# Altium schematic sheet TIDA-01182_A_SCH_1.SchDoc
size 431 x 279 mm; Date: Not shown in title block; ApprovedBy: Not shown in title block; CheckedBy: Not shown in title block; Author: Not shown in title block; CompanyName: Not shown in title block; DrawnBy: Gordon Varney; Engineer: Not shown in title block; Organization: Not shown in title block; Address1: Not shown in title block; Address2: Not shown in title block; Address3: Not shown in title block; Address4: Not shown in title block; DocumentNumber: 1; Revision: Use project parameter SCH_Rev; SheetNumber: 2; SheetTotal: 4; PageSetup: Record=PageOptions¦CenterHorizontal=True¦CenterVertical=True¦PrintScale=0.70¦XCorrection=1.00¦YCorrection=1.00¦PrintKind=0¦BorderSize=5000000¦LeftOffset=0¦BottomOffset=0¦Orientation=2¦PaperLength=1000¦PaperWidth=1000¦Scale=100¦PaperSource=15¦PrintQuality=1200¦MediaType=1¦DitherType=10¦PrintScaleMode=1¦PaperKind=Letter¦PaperIndex=1
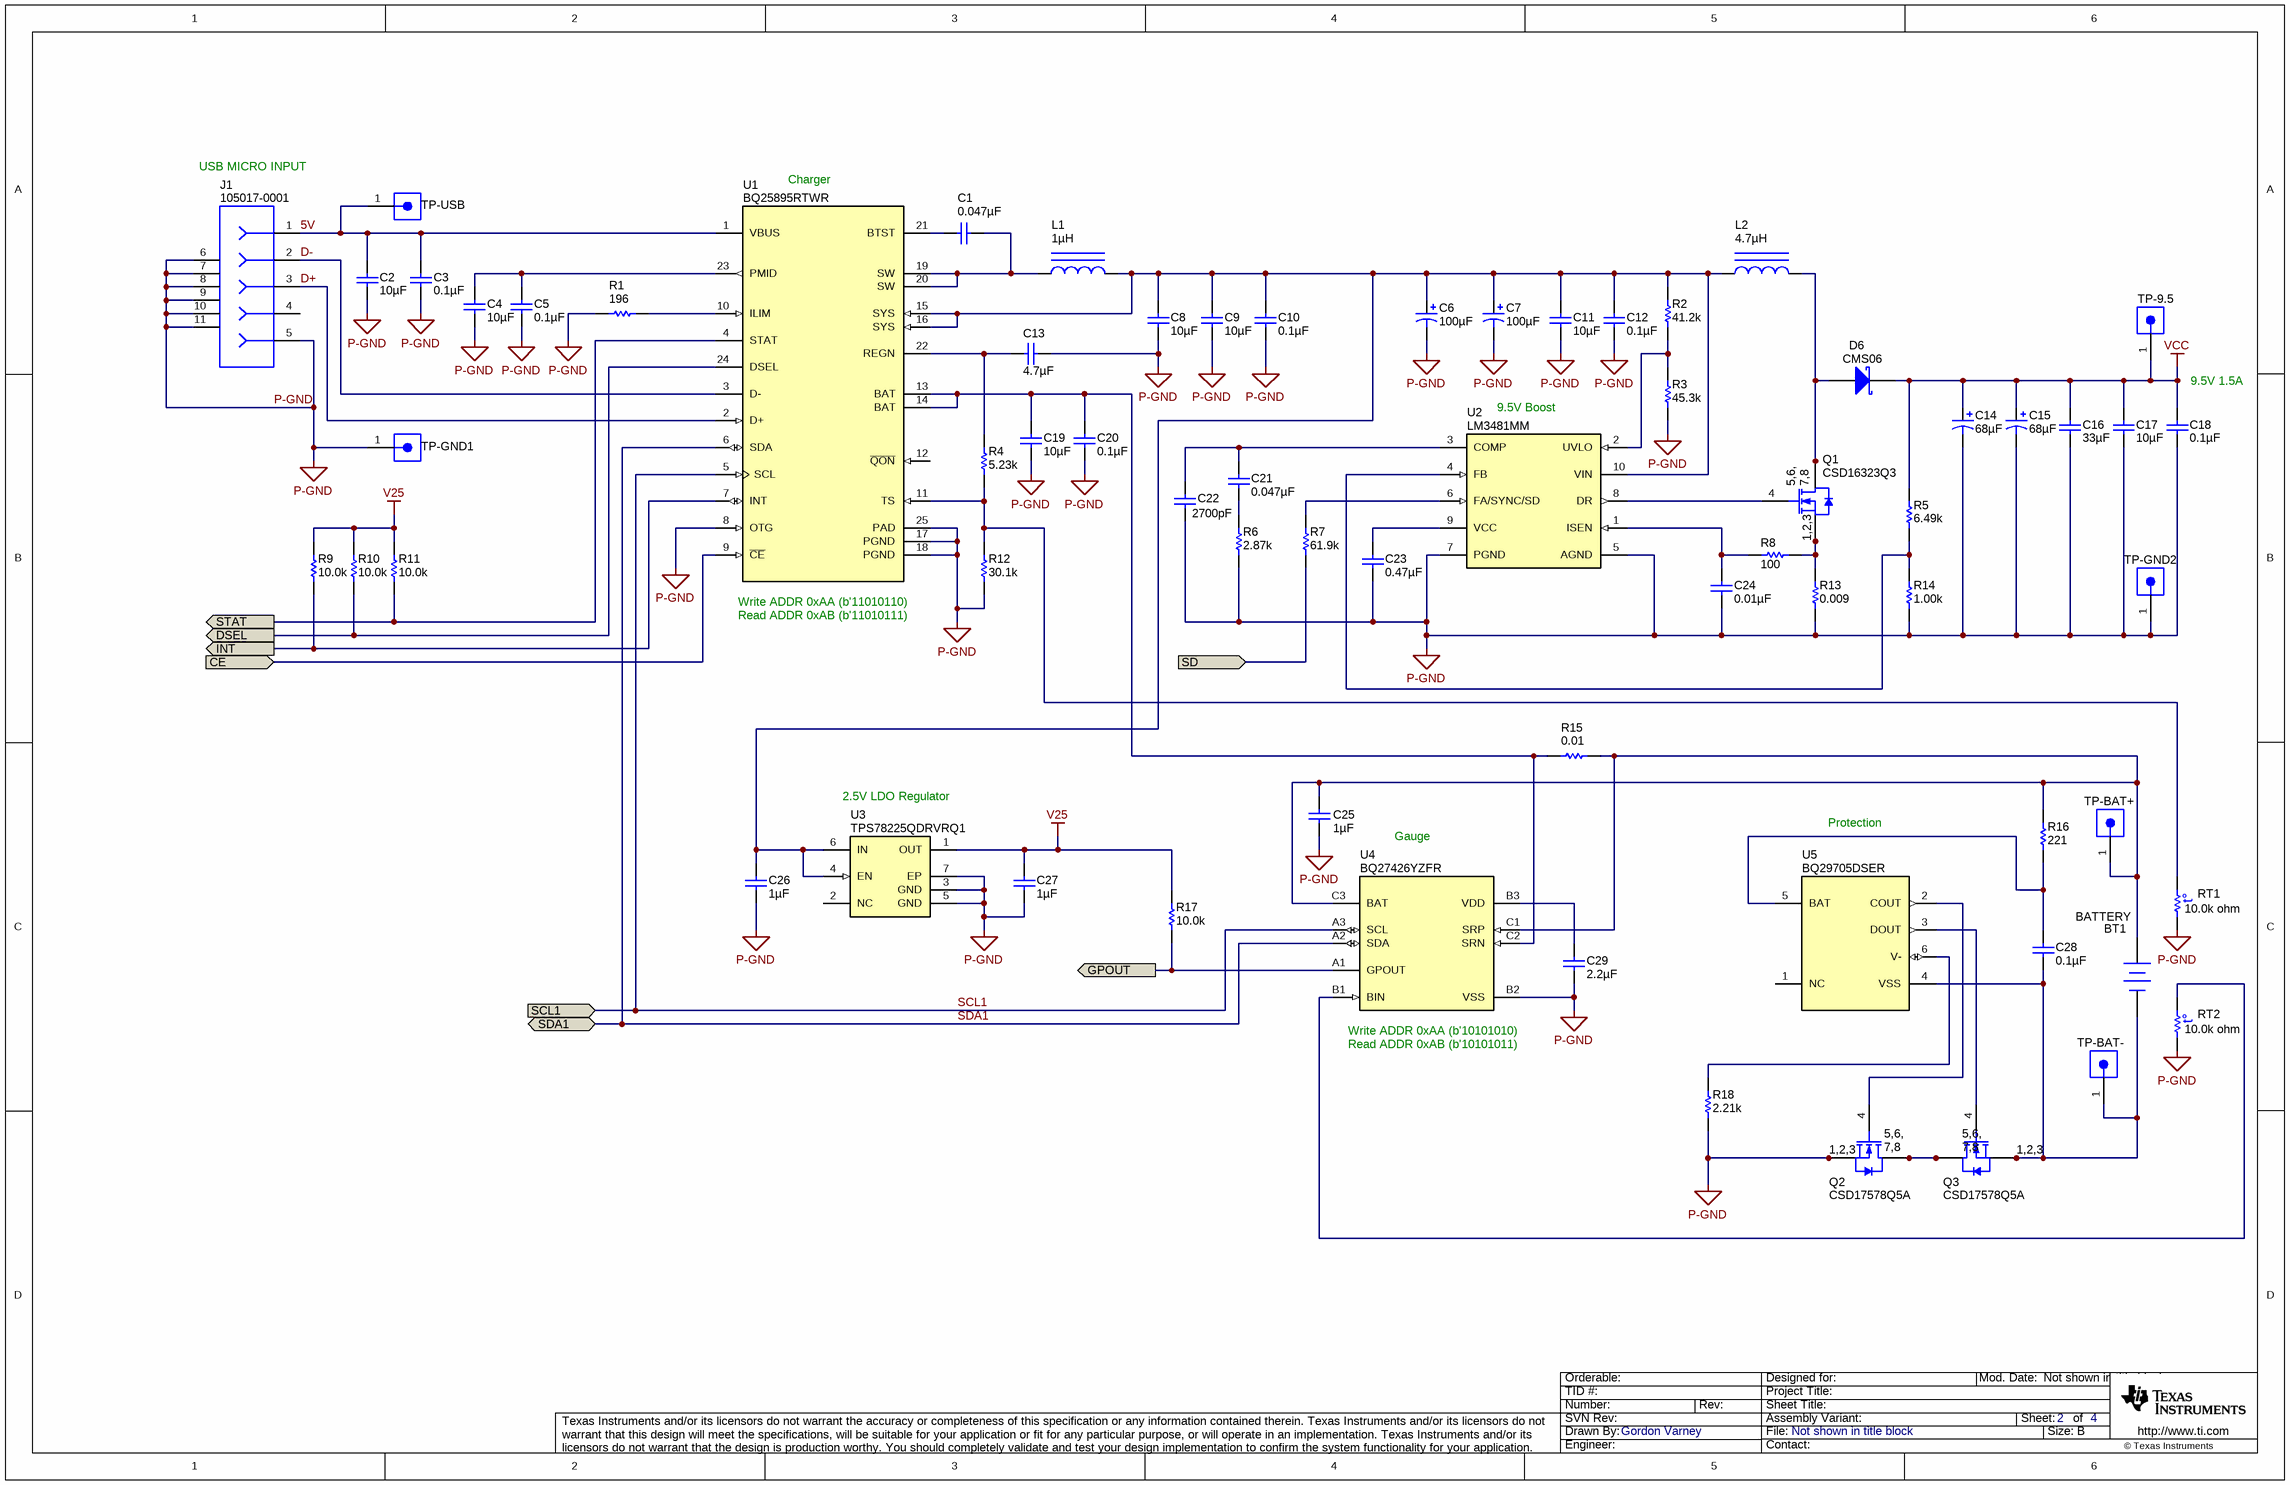
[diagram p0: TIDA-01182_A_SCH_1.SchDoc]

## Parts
BT1  1043  [BAT_1043]  (value not drawn)
C1  ValueDisplayed: 0.047µF  [0402]  (hidden comment: GRM155R71E473KA88D)
C2  ValueDisplayed: 10µF  [1206]  (hidden comment: 885012208069)
C3  ValueDisplayed: 0.1µF  [0603]  (hidden comment: 885012206071)
C4  ValueDisplayed: 10µF  [1206]  (hidden comment: 885012208069)
C5  ValueDisplayed: 0.1µF  [0603]  (hidden comment: 885012206071)
C6  ValueDisplayed: 100µF  [SM_RADIAL_E]  (hidden comment: EEE-FK1E101P)
C7  ValueDisplayed: 100µF  [SM_RADIAL_E]  (hidden comment: EEE-FK1E101P)
C8  ValueDisplayed: 10µF  [1206]  (hidden comment: 885012208069)
C9  ValueDisplayed: 10µF  [1206]  (hidden comment: 885012208069)
C10  ValueDisplayed: 0.1µF  [0603]  (hidden comment: 885012206071)
C11  ValueDisplayed: 10µF  [1206]  (hidden comment: 885012208069)
C12  ValueDisplayed: 0.1µF  [0603]  (hidden comment: 885012206071)
C13  ValueDisplayed: 4.7µF  [0805_HV]  (hidden comment: 885012207025)
C14  ValueDisplayed: 68µF  [SM_RADIAL_F]  (hidden comment: EEE-FC1E680P)
C15  ValueDisplayed: 68µF  [SM_RADIAL_F]  (hidden comment: EEE-FC1E680P)
C16  ValueDisplayed: 33µF  [1206_180]  (hidden comment: C3216X5R1E336M160AC)
C17  ValueDisplayed: 10µF  [1206]  (hidden comment: 885012208069)
C18  ValueDisplayed: 0.1µF  [0603]  (hidden comment: 885012206071)
C19  ValueDisplayed: 10µF  [1206]  (hidden comment: 885012208069)
C20  ValueDisplayed: 0.1µF  [0603]  (hidden comment: 885012206071)
C21  ValueDisplayed: 0.047µF  [0402]  (hidden comment: C1005X7R1H473K050BB)
C22  ValueDisplayed: 2700pF  [0402]  (hidden comment: GRM155R71H272KA01D)
C23  ValueDisplayed: 0.47µF  [0603]  (hidden comment: GRM188R71C474KA88D)
C24  ValueDisplayed: 0.01µF  [0402]  (hidden comment: 885012205031)
C25  ValueDisplayed: 1µF  [0402]  (hidden comment: GRM155R61A105KE15D)
C26  ValueDisplayed: 1µF  [0603]  (hidden comment: C0603C105K3RACTU)
C27  ValueDisplayed: 1µF  [0603]  (hidden comment: C0603C105K3RACTU)
C28  ValueDisplayed: 0.1µF  [0402]  (hidden comment: GRM155R71A104KA01D)
C29  ValueDisplayed: 2.2µF  [0402]  (hidden comment: GRM155R61C225KE11D)
D6  CMS06  [M-FLAT]
J1  105017-0001  [CONN_105017-0001]
L1  ValueDisplayed: 1µH  [IHLP-2020BZ]  (hidden comment: IHLP2020BZER1R0M11)
L2  ValueDisplayed: 4.7µH  [SRR1280]  (hidden comment: SRR1280-4R7Y)
Q1  CSD16323Q3  [DQG0008A]
Q2  CSD17578Q5A  [TRANS_NexFET_Q5A]
Q3  CSD17578Q5A  [TRANS_NexFET_Q5A]
R1  ValueDisplayed: 196  [0402]  (hidden comment: CRCW0402196RFKED)
R2  ValueDisplayed: 41.2k  [0402]  (hidden comment: CRCW040241K2FKED)
R3  ValueDisplayed: 45.3k  [0402]  (hidden comment: CRCW040245K3FKED)
R4  ValueDisplayed: 5.23k  [0402]  (hidden comment: CRCW04025K23FKED)
R5  ValueDisplayed: 6.49k  [0402]  (hidden comment: CRCW04026K49FKED)
R6  ValueDisplayed: 2.87k  [0402]  (hidden comment: CRCW04022K87FKED)
R7  ValueDisplayed: 61.9k  [0402]  (hidden comment: CRCW040261K9FKED)
R8  ValueDisplayed: 100  [0402]  (hidden comment: CRCW0402100RFKED)
R9  ValueDisplayed: 10.0k  [0402]  (hidden comment: CRCW040210K0FKED)
R10  ValueDisplayed: 10.0k  [0402]  (hidden comment: CRCW040210K0FKED)
R11  ValueDisplayed: 10.0k  [0402]  (hidden comment: CRCW040210K0FKED)
R12  ValueDisplayed: 30.1k  [0402]  (hidden comment: CRCW040230K1FKED)
R13  ValueDisplayed: 0.009  [0612]  (hidden comment: PRL1632-R009-F-T1)
R14  ValueDisplayed: 1.00k  [0402]  (hidden comment: CRCW04021K00FKED)
R15  ValueDisplayed: 0.01  [0612]  (hidden comment: PRL1632-R010-F-T1)
R16  ValueDisplayed: 221  [0402]  (hidden comment: CRCW0402221RFKED)
R17  ValueDisplayed: 10.0k  [0402]  (hidden comment: CRCW040210K0FKED)
R18  ValueDisplayed: 2.21k  [0402]  (hidden comment: CRCW04022K21FKED)
RT1  value 10.0k ohm  [0603]  (hidden comment: ERT-J1VG103FA)
RT2  value 10.0k ohm  [0603]  (hidden comment: ERT-J1VG103FA)
TP-9.5  61300111121  [WURTH_61300111121]  (value not drawn)
TP-BAT+  61300111121  [WURTH_61300111121]  (value not drawn)
TP-BAT-  61300111121  [WURTH_61300111121]  (value not drawn)
TP-GND1  61300111121  [WURTH_61300111121]  (value not drawn)
TP-GND2  61300111121  [WURTH_61300111121]  (value not drawn)
TP-USB  61300111121  [WURTH_61300111121]  (value not drawn)
U1  BQ25895RTWR  [RTW0024H]
U2  LM3481MM  [MUB10A_N]
U3  TPS78225QDRVRQ1  [DRV0006A]
U4  BQ27426YZFR  [YZF0009-C01]
U5  BQ29705DSER  [DSE0006A]

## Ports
CE, DSEL, GPOUT, INT, SCL1, SD, SDA1, STAT

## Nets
P-GND: C2.2 C3.2 C4.2 C5.2 C6.2(-) C7.2(-) C8.2 C9.2 C10.2 C11.2 C12.2 C13.2 C14.2(-) C15.2(-) C16.2 C17.2 C18.2 C19.2 C20.2 C22.2 C23.2 C24.2 C25.2 C26.2 C27.2 C29.2 J1.5 J1.6 J1.7 J1.8 J1.9 J1.10 J1.11 Q2.1(S) Q2.2(S) Q2.3(S) R1.2 R3.1 R6.1 R12.1 R13.1 R14.1 R18.1 RT1.1 RT2.1 TP-GND1.1 TP-GND2.1 U1.8(OTG) U1.17(PGND) U1.18(PGND) U1.25(PAD) U2.5(AGND) U2.7(PGND) U3.3(GND) U3.5(GND) U3.7(EP) U4.B2(VSS)
V25: C27.1 R9.2 R10.2 R11.2 R17.2 U3.1(OUT)
VCC: C14.1(+) C15.1(+) C16.1 C17.1 C18.1 D6.1(K) R5.2 TP-9.5.1
5V: C2.1 C3.1 J1.1 TP-USB.1 U1.1(VBUS)
CE: U1.9(~{CE}) ; port CE
D+: J1.3 U1.2(D+)
D-: J1.2 U1.3(D-)
DSEL: R10.1 U1.24(DSEL) ; port DSEL
GPOUT: R17.1 U4.A1(GPOUT) ; port GPOUT
INT: R9.1 U1.7(INT) ; port INT
SCL1: U1.5(SCL) U4.A3(SCL) ; port SCL1
SD: R7.1 ; port SD
SDA1: U1.6(SDA) U4.A2(SDA) ; port SDA1
STAT: R11.1 U1.4(STAT) ; port STAT
NetBT1_1: BT1.1(+) C25.1 R15.2 R16.2 TP-BAT+.1 U4.C1(SRP) U4.C3(BAT)
NetBT1_2: BT1.2(-) C28.2 Q3.1(S) Q3.2(S) Q3.3(S) TP-BAT-.1 U5.4(VSS)
NetC1_1: C1.1 L1.1 U1.19(SW) U1.20(SW)
NetC1_2: C1.2 U1.21(BTST)
NetC4_1: C4.1 C5.1 U1.23(PMID)
NetC6_1: C6.1(+) C7.1(+) C8.1 C9.1 C10.1 C11.1 C12.1 C26.1 L1.2 L2.1 R2.2 U1.15(SYS) U1.16(SYS) U2.10(VIN) U3.4(EN) U3.6(IN)
NetC13_1: C13.1 R4.2 U1.22(REGN)
NetC19_1: C19.1 C20.1 R15.1 U1.13(BAT) U1.14(BAT) U4.C2(SRN)
NetC21_1: C21.1 C22.1 U2.3(COMP)
NetC21_2: C21.2 R6.2
NetC23_1: C23.1 U2.9(VCC)
NetC24_1: C24.1 R8.1 U2.1(ISEN)
NetC28_1: C28.1 R16.1 U5.5(BAT)
NetC29_1: C29.1 U4.B3(VDD)
NetD6_2: D6.2(A) L2.2 Q1.5(D) Q1.6(D) Q1.7(D) Q1.8(D) Q1.9(D)
NetQ1_1: Q1.1(S) Q1.2(S) Q1.3(S) R8.2 R13.2
NetQ1_4: Q1.4(G) U2.8(DR)
NetQ2_4: Q2.4(G) U5.2(COUT)
NetQ2_5: Q2.5(D) Q2.6(D) Q2.7(D) Q2.8(D) Q2.9(D) Q3.5(D) Q3.6(D) Q3.7(D) Q3.8(D) Q3.9(D)
NetQ3_4: Q3.4(G) U5.3(DOUT)
NetR1_1: R1.1 U1.10(ILIM)
NetR2_1: R2.1 R3.2 U2.2(UVLO)
NetR4_1: R4.1 R12.2 RT1.2 U1.11(TS)
NetR5_1: R5.1 R14.2 U2.4(FB)
NetR7_2: R7.2 U2.6(FA/SYNC/SD)
NetR18_2: R18.2 U5.6(V-)
NetRT2_2: RT2.2 U4.B1(BIN)

Not connected (* = marked no-connect by the designer): J1 4; U1 12(~{QON}); U3 2(NC); U5 1(NC)

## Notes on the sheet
- USB MICRO INPUT
- (near U1) Charger
- (near U2) 9.5V Boost
- 9.5V 1.5A
- (near U1) Write ADDR 0xAA (b'11010110)
- Read ADDR 0xAB (b'11010111)
- (near U3) 2.5V LDO Regulator
- Gauge
- Protection
- BATTERY
- (near U4) Write ADDR 0xAA (b'10101010)
- (near U4) Read ADDR 0xAB (b'10101011)

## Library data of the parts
BT1 = 1043: Battery Holder, Plastic, 18650, TH; Manufacturer: Keystone
C1 = GRM155R71E473KA88D: CAP, CERM, 0.047 µF, 25 V, +/- 10%, X7R, 0402; Manufacturer: MuRata; Polarized: N; CompType: Capacitor; Value: 0.047uF; U/M: EA; Cap_F: 0.000000047; Tolerance_%: 10; Value1: Unknown; VDC_V: 25; Value2: 25V; TaMin_C: -55; TaMax_C: 125; SizeArea_mm2: 0.5; SizeAreaWB_mm2: 3; SizeX_mm: 1; SizeZ_mm: 0.6; AEC Category: Q200
C2 C4 C8 C9 C11 C17 C19 = 885012208069: CAP, CERM, 10 µF, 25 V, +/- 10%, X7R, 1206; Manufacturer: Wurth Elektronik; Polarized: N; CompType: Capacitor; Value: 10uF; U/M: EA; Cap_F: 0.00001; Tolerance_%: 10; Value1: Unknown; VDC_V: 25; Value2: 25V; TaMin_C: -55; TaMax_C: 125; SizeArea_mm2: 5.12; SizeAreaWB_mm2: 10.92; SizeX_mm: 3.2; SizeY_mm: 1.6; SizeZ_mm: 1.35; AEC Category: Q200
C3 C5 C10 C12 C18 C20 = 885012206071: CAP, CERM, 0.1 µF, 25 V, +/- 10%, X7R, 0603; Manufacturer: Wurth Elektronik; Polarized: N; CompType: Capacitor; Value: 0.1uF; U/M: EA; Cap_F: 0.0000001; Tolerance_%: 10; Value1: Unknown; VDC_V: 25; Value2: 25V; TaMin_C: -55; TaMax_C: 125; SizeArea_mm2: 1.28; SizeAreaWB_mm2: 4.68; SizeX_mm: 1.6; SizeY_mm: 0.8; SizeZ_mm: 1; AEC Category: Q200
C6 C7 = EEE-FK1E101P: CAP, AL, 100 µF, 25 V, +/- 20%, 0.26 ohm, SMD; Manufacturer: Panasonic; Polarized: Y; CompType: Capacitor; Value: 100uF; U/M: EA; Cap_F: 0.0001; Tolerance_%: 20; VDC_V: 25; Value2: 25V; ESR_ohm: 0.26; IRMS_A: 0.3; TaMin_C: -55; TaMax_C: 105; Cap_Case: E; AEC Category: Q200
C13 = 885012207025: CAP, CERM, 4.7 µF, 10 V, +/- 10%, X7R, 0805; Manufacturer: Wurth Elektronik; Polarized: N; CompType: Capacitor; Value: 4.7uF; U/M: EA; Cap_F: 0.0000047; Tolerance_%: 10; Value1: Unknown; Value2: 10V; TaMin_C: -55; TaMax_C: 125; Cap_Case: 0805; SizeArea_mm2: 2.5; SizeAreaWB_mm2: 6.75; SizeX_mm: 2; SizeY_mm: 1.25; SizeZ_mm: 1.45; AEC Category: Q200
C14 C15 = EEE-FC1E680P: CAP, AL, 68 µF, 25 V, +/- 20%, 0.3 ohm, SMD; Manufacturer: Panasonic; Polarized: Y; CompType: Capacitor; Value: 68uF; U/M: EA; Cap_F: 0.000068; Tolerance_%: 20; Value1: 0.3 ohm; VDC_V: 25; Value2: 25V; ESR_ohm: 0.3; IRMS_A: 0.18; TaMin_C: -40; TaMax_C: 105; Cap_Case: F; AEC Category: Q200
C16 = C3216X5R1E336M160AC: CAP, CERM, 33 µF, 25 V, +/- 20%, X5R, 1206; Manufacturer: TDK; Polarized: N; CompType: Capacitor; Value: 33uF; U/M: EA; Cap_F: 0.000033; Tolerance_%: 20; ESR_ohm: 0.002648; Value1: 0.002648 ohm; VDC_V: 25; Value2: 25V; IRMS_A: 4.45864; TaMin_C: -55; TaMax_C: 85; SizeArea_mm2: 5.12; SizeAreaWB_mm2: 10.92; SizeX_mm: 3.2; SizeY_mm: 1.6; SizeZ_mm: 1.8; AEC Category: Q200
C21 = C1005X7R1H473K050BB: CAP, CERM, 0.047 µF, 50 V, +/- 10%, X7R, 0402; Manufacturer: TDK; Polarized: N; CompType: Capacitor; Value: 0.047uF; U/M: EA; Cap_F: 0.000000047; Tolerance_%: 10; ESR_ohm: 0.06407; Value1: 0.06407 ohm; VDC_V: 50; Value2: 50V; IRMS_A: 0.646122; TaMin_C: -55; TaMax_C: 125; SizeArea_mm2: 0.5; SizeAreaWB_mm2: 3; SizeX_mm: 1; SizeZ_mm: 0.6; AEC Category: Q200
C22 = GRM155R71H272KA01D: CAP, CERM, 2700 pF, 50 V, +/- 10%, X7R, 0402; Manufacturer: MuRata; Polarized: N; CompType: Capacitor; Value: 2700pF; U/M: EA; Cap_F: 0.0000000027; Tolerance_%: 10; Value1: Unknown; VDC_V: 50; Value2: 50V; TaMin_C: -55; TaMax_C: 125; SizeArea_mm2: 0.5; SizeAreaWB_mm2: 3; SizeX_mm: 1; SizeZ_mm: 0.6; AEC Category: Q200
C23 = GRM188R71C474KA88D: CAP, CERM, 0.47 µF, 16 V, +/- 10%, X7R, 0603; Manufacturer: MuRata; Polarized: N; CompType: Capacitor; Value: 0.47uF; U/M: EA; Cap_F: 0.00000047; Tolerance_%: 10; Value1: Unknown; VDC_V: 16; Value2: 16V; TaMin_C: -55; TaMax_C: 125; SizeArea_mm2: 1.28; SizeAreaWB_mm2: 4.68; SizeX_mm: 1.6; SizeY_mm: 0.8; SizeZ_mm: 1; AEC Category: Q200
C24 = 885012205031: CAP, CERM, 0.01 µF, 16 V, +/- 10%, X7R, 0402; Manufacturer: Wurth Elektronik; Polarized: N; CompType: Capacitor; Value: 0.01uF; U/M: EA; Cap_F: 0.00000001; Tolerance_%: 10; Value1: Unknown; VDC_V: 16; Value2: 16V; TaMin_C: -55; TaMax_C: 125; SizeArea_mm2: 0.5; SizeAreaWB_mm2: 3; SizeX_mm: 1; SizeZ_mm: 0.6; AEC Category: Q200
C25 = GRM155R61A105KE15D: CAP, CERM, 1 µF, 10 V, +/- 10%, X5R, 0402; Manufacturer: MuRata; Polarized: N; CompType: Capacitor; Value: 1uF; U/M: EA; Cap_F: 0.000001; Tolerance_%: 10; Value1: Unknown; Value2: 10V; TaMin_C: -55; TaMax_C: 85; SizeArea_mm2: 0.5; SizeAreaWB_mm2: 3; SizeX_mm: 1; SizeZ_mm: 0.6; AEC Category: Q200
C26 C27 = C0603C105K3RACTU: CAP, CERM, 1 µF, 25 V, +/- 10%, X7R, 0603; Manufacturer: Kemet; Polarized: N; CompType: Capacitor; Value: 1uF; U/M: EA; Cap_F: 0.000001; Tolerance_%: 10; Value1: Unknown; VDC_V: 25; Value2: 25V; TaMin_C: -55; TaMax_C: 125; SizeArea_mm2: 1.28; SizeAreaWB_mm2: 4.68; SizeX_mm: 1.6; SizeY_mm: 0.8; SizeZ_mm: 1; AEC Category: Q200
C28 = GRM155R71A104KA01D: CAP, CERM, 0.1 µF, 10 V, +/- 10%, X7R, 0402; Manufacturer: MuRata; Polarized: N; CompType: Capacitor; Value: 0.1uF; U/M: EA; Cap_F: 0.0000001; Tolerance_%: 10; Value1: Unknown; Value2: 10V; TaMin_C: -55; TaMax_C: 125; SizeArea_mm2: 0.5; SizeAreaWB_mm2: 3; SizeX_mm: 1; SizeZ_mm: 0.6; AEC Category: Q200
C29 = GRM155R61C225KE11D: CAP, CERM, 2.2 µF, 16 V, +/- 10%, X5R, 0402; Manufacturer: MuRata; Polarized: N; CompType: Capacitor; Value: 2.2uF; U/M: EA; Cap_F: 0.0000022; Tolerance_%: 10; Value1: Unknown; VDC_V: 16; Value2: 16V; TaMin_C: -55; TaMax_C: 85; SizeArea_mm2: 0.5; SizeAreaWB_mm2: 3; SizeX_mm: 1; SizeZ_mm: 0.6; AEC Category: Q200
D6 = CMS06: Diode, Schottky, 30 V, 2 A, M-FLAT; Manufacturer: Toshiba; U/M: EA; Vf_V: 0.32; Value: 30V; Value1: 2A; Value2: 0.32V; Io_A: 2; Vr_V: 30; TJmax_C: 125; RJC_CperW: 16; SizeAreaWB_mm2: 19.38; SizeArea_mm2: 11.28; SizeX_mm: 4.7; SizeY_mm: 2.4; SizeZ_mm: 0.98; AEC Category: Q101
J1 = 105017-0001: Connector, Receptacle, Micro-USB Type B, R/A, Bottom Mount SMT; Manufacturer: Molex; SymbolCreator: a0412235
L1 = IHLP2020BZER1R0M11: Inductor, Shielded Drum Core, Powdered Iron, 1 µH, 7 A, 0.0181 ohm, SMD; Manufacturer: Vishay-Dale; Value: 1uH; Ind_H: 1.0E-6; Imax_A: 7; Irms: 7.5A @ 40C rise; Isat: 7A @ 20% inductance drop; DCR_ohm: 0.0181; Value2: 7A; AEC Category: Q200
L2 = SRR1280-4R7Y: Inductor, Drum Core, Ferrite, 4.7 µH, 8.2 A, 0.0155 ohm, SMD; Manufacturer: Bourns; Value: 4.7uH; Ind_H: 4.7E-6; Imax_A: 8.2; Irms: 8.2A @ 40C rise; Isat: 8.8A @ 25% inductance drop; DCR_ohm: 0.0155; Value2: 8.2A; AEC Category: Q200
Q1 = CSD16323Q3: MOSFET, N-CH, 25 V, 60 A, VSON-CLIP-8; Manufacturer: Texas Instruments; Alternate Manufacturer: None; U/M: EA; ChType: N; Value: 25V; VdsMax_V: 25; Value1: 0.0044 ohm; Rdson45_ohm: 0.0044; Value2: 6.2 nC; QgTyp_nC: 6.2; Vgs_V: 10; IdsMax_A: 60; SizeAreaWB_mm2: 18.49; SizeArea_mm2: 10.89; SizeX_mm: 3.3; SizeZ_mm: 1.1; AEC Category: Q101
Q2 Q3 = CSD17578Q5A: MOSFET, N-CH, 30 V, 25 A, SON 5x6mm; Manufacturer: Texas Instruments; Alternate Manufacturer: None; U/M: EA; ChType: N; Value: 30V; VdsMax_V: 30; Value1: 0.0093 ohm; Rdson45_ohm: 0.0093; Value2: 17.2 nC; QgTyp_nC: 17.2; Vgs_V: 20; IdsMax_A: 25; SizeAreaWB_mm2: 55.2; SizeArea_mm2: 29.4; SizeX_mm: 6; SizeY_mm: 4.9; SizeZ_mm: 1; AEC Category: Q101
R1 = CRCW0402196RFKED: RES, 196, 1%, 0.063 W, 0402; Manufacturer: Vishay-Dale; CompType: Resistor; Value: 196; Value_Code: 196R; Tolerance_%: 1; Power_W: 0.063; Value2: 0.063W; VDC_V: 50; TempCo: 100 ppm/C; SizeArea_mm2: 0.5; SizeZ_mm: 0.6; EIA_Code: E96; U/M: EA; AEC Category: Q200
R2 = CRCW040241K2FKED: RES, 41.2 k, 1%, 0.063 W, 0402; Manufacturer: Vishay-Dale; CompType: Resistor; Value: 41.2k; Res_ohm: 41200; Value_Code: 41k2; Tolerance_%: 1; Power_W: 0.063; Value2: 0.063W; VDC_V: 50; TempCo: 100 ppm/C; SizeArea_mm2: 0.5; SizeZ_mm: 0.6; EIA_Code: E96; U/M: EA; AEC Category: Q200
R3 = CRCW040245K3FKED: RES, 45.3 k, 1%, 0.063 W, 0402; Manufacturer: Vishay-Dale; CompType: Resistor; Value: 45.3k; Res_ohm: 45300; Value_Code: 45k3; Tolerance_%: 1; Power_W: 0.063; Value2: 0.063W; VDC_V: 50; TempCo: 100 ppm/C; SizeArea_mm2: 0.5; SizeZ_mm: 0.6; EIA_Code: E96; U/M: EA; AEC Category: Q200
R4 = CRCW04025K23FKED: RES, 5.23 k, 1%, 0.063 W, 0402; Manufacturer: Vishay-Dale; CompType: Resistor; Value: 5.23k; Res_ohm: 5230; Value_Code: 5k23; Tolerance_%: 1; Power_W: 0.063; Value2: 0.063W; VDC_V: 50; TempCo: 100 ppm/C; SizeArea_mm2: 0.5; SizeZ_mm: 0.6; EIA_Code: E96; U/M: EA; AEC Category: Q200
R5 = CRCW04026K49FKED: RES, 6.49 k, 1%, 0.063 W, 0402; Manufacturer: Vishay-Dale; CompType: Resistor; Value: 6.49k; Res_ohm: 6490; Value_Code: 6k49; Tolerance_%: 1; Power_W: 0.063; Value2: 0.063W; VDC_V: 50; TempCo: 100 ppm/C; SizeArea_mm2: 0.5; SizeZ_mm: 0.6; EIA_Code: E96; U/M: EA; AEC Category: Q200
R6 = CRCW04022K87FKED: RES, 2.87 k, 1%, 0.063 W, 0402; Manufacturer: Vishay-Dale; CompType: Resistor; Value: 2.87k; Res_ohm: 2870; Value_Code: 2k87; Tolerance_%: 1; Power_W: 0.063; Value2: 0.063W; VDC_V: 50; TempCo: 100 ppm/C; SizeArea_mm2: 0.5; SizeZ_mm: 0.6; EIA_Code: E96; U/M: EA; AEC Category: Q200
R7 = CRCW040261K9FKED: RES, 61.9 k, 1%, 0.063 W, 0402; Manufacturer: Vishay-Dale; CompType: Resistor; Value: 61.9k; Res_ohm: 61900; Value_Code: 61k9; Tolerance_%: 1; Power_W: 0.063; Value2: 0.063W; VDC_V: 50; TempCo: 100 ppm/C; SizeArea_mm2: 0.5; SizeZ_mm: 0.6; EIA_Code: E96; U/M: EA; AEC Category: Q200
R8 = CRCW0402100RFKED: RES, 100, 1%, 0.063 W, 0402; Manufacturer: Vishay-Dale; CompType: Resistor; Value: 100; Value_Code: 100R; Tolerance_%: 1; Power_W: 0.063; Value2: 0.063W; VDC_V: 50; TempCo: 100 ppm/C; SizeArea_mm2: 0.5; SizeZ_mm: 0.6; EIA_Code: E96; U/M: EA; AEC Category: Q200
R9-R11 R17 = CRCW040210K0FKED: RES, 10.0 k, 1%, 0.063 W, 0402; Manufacturer: Vishay-Dale; CompType: Resistor; Value: 10.0k; Res_ohm: 10000; Value_Code: 10k0; Tolerance_%: 1; Power_W: 0.063; Value2: 0.063W; VDC_V: 50; TempCo: 100 ppm/C; EIA_Code: E96; U/M: EA; SizeArea_mm2: 0.5; SizeZ_mm: 0.6; AEC Category: Q200
R12 = CRCW040230K1FKED: RES, 30.1 k, 1%, 0.063 W, 0402; Manufacturer: Vishay-Dale; CompType: Resistor; Value: 30.1k; Res_ohm: 30100; Value_Code: 30k1; Tolerance_%: 1; Power_W: 0.063; Value2: 0.063W; VDC_V: 50; TempCo: 100 ppm/C; SizeArea_mm2: 0.5; SizeZ_mm: 0.6; EIA_Code: E96; U/M: EA; AEC Category: Q200
R13 = PRL1632-R009-F-T1: RES, 0.009, 1%, 1 W, 0612; Manufacturer: Susumu Co Ltd; CompType: Resistor; Value: 0.009; Value_Code: 9L000; Tolerance_%: 1; Value2: 1W; TempCo: 350 ppm/C; SizeArea_mm2: 5.12; SizeAreaWB_mm2: 10.92; SizeX_mm: 1.6; SizeY_mm: 3.2; SizeZ_mm: 0.85; EIA_Code: E96; U/M: EA; AEC Category: Q200
R14 = CRCW04021K00FKED: RES, 1.00 k, 1%, 0.063 W, 0402; Manufacturer: Vishay-Dale; CompType: Resistor; Value: 1.00k; Res_ohm: 1000; Value_Code: 1k00; Tolerance_%: 1; Power_W: 0.063; Value2: 0.063W; VDC_V: 50; TempCo: 100 ppm/C; SizeArea_mm2: 0.5; SizeZ_mm: 0.6; EIA_Code: E96; U/M: EA; AEC Category: Q200
R15 = PRL1632-R010-F-T1: RES, 0.01, 1%, 1 W, 0612; Manufacturer: Susumu Co Ltd; CompType: Resistor; Value: 0.01; Value_Code: R010; Tolerance_%: 1; Value2: 1W; TempCo: 200 ppm/C; SizeArea_mm2: 5.12; SizeAreaWB_mm2: 10.92; SizeX_mm: 1.6; SizeY_mm: 3.2; SizeZ_mm: 0.85; EIA_Code: E96; U/M: EA; AEC Category: Q200
R16 = CRCW0402221RFKED: RES, 221, 1%, 0.063 W, 0402; Manufacturer: Vishay-Dale; CompType: Resistor; Value: 221; Value_Code: 221R; Tolerance_%: 1; Power_W: 0.063; Value2: 0.063W; VDC_V: 50; TempCo: 100 ppm/C; EIA_Code: E96; U/M: EA; SizeArea_mm2: 0.5; SizeZ_mm: 0.6; AEC Category: Q200
R18 = CRCW04022K21FKED: RES, 2.21 k, 1%, 0.063 W, 0402; Manufacturer: Vishay-Dale; CompType: Resistor; Value: 2.21k; Res_ohm: 2210; Value_Code: 2k21; Tolerance_%: 1; Power_W: 0.063; Value2: 0.063W; VDC_V: 50; TempCo: 100 ppm/C; EIA_Code: E96; U/M: EA; SizeArea_mm2: 0.5; SizeZ_mm: 0.6; AEC Category: Q200
RT1 RT2 = ERT-J1VG103FA: Thermistor NTC, 10.0k ohm, 1%, 0603; Manufacturer: Panasonic; Tolerance_%: 1; Power_W: 0.1; TaMin_C: -40; TaMax_C: 125; U/M: EA
TP-9.5 TP-BAT+ TP-BAT- TP-GND1 TP-GND2 TP-USB = 61300111121: Header, 2.54 mm, 1x1, Gold, TH; Manufacturer: Wurth Elektronik; SymbolCreator: a0412235
U1 = BQ25895RTWR: I2C Controlled 5A Single Cell Charger with NVDC Power Path Management and MaxChargeTM High Voltage Adapter Support, RTW0024H; Alternate PartNumber: BQ25895RTWT; Manufacturer: Texas Instruments; SymbolCreator: Altium; SizeArea_mm2: 16; SizeAreaWB_mm2: 25; SizeX_mm: 4; SizeZ_mm: 0.8; CompType: IC; U/M: EA
U2 = LM3481MM: High Efficiency Low-Side N-Channel Controller for Switching Regulators, 10-pin MSOP; Manufacturer: Texas Instruments; PackageTopMarking: ZXTT*SJPB; PowerWise: N; CompType: MiscPower
U3 = TPS78225QDRVRQ1: Single Output Automotive LDO, 150 mA, Fixed 2.5 V Output, 2.2 to 5.5 V Input, with 1 uA Quiescent Current, 6-pin SON (DRV), -40 to 125 degC, Green (RoHS & no Sb/Br); Manufacturer: Texas Instruments; Alternate PartNumber: Equivalent; Accuracy(%): 3; Fixed Output Options(V): 2.5; Iout(Max)(A): 0.15; Iq(Typ)(mA): 0.001; SubFamily: Single Channel LDO; Vdo(Typ)(mV): 130; Vin(Max)(V): 5.5; Vin(Min)(V): 2.2
U4 = BQ27426YZFR: System-Side Impedance Track Fuel Gauge, YZF0009-C01; Alternate PartNumber: BQ27426YZFT; Manufacturer: Texas Instruments; SymbolCreator: Altium; SizeArea_mm2: 2.5596; SizeAreaWB_mm2: 6.7596; SizeX_mm: 1.62; SizeY_mm: 1.58; SizeZ_mm: 0.625; CompType: IC; U/M: EA
U5 = BQ29705DSER: Cost-Effective Voltage and Current Protection Integrated Circuit for Single-Cell Li-Ion and Li-Polymer Batteries , DSE0006A; Alternate PartNumber: BQ29705DSET; Manufacturer: Texas Instruments; SymbolCreator: a0412235; SizeArea_mm2: 2.25; SizeAreaWB_mm2: 6.25; SizeX_mm: 1.5; SizeZ_mm: 0.8; CompType: IC; U/M: EA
